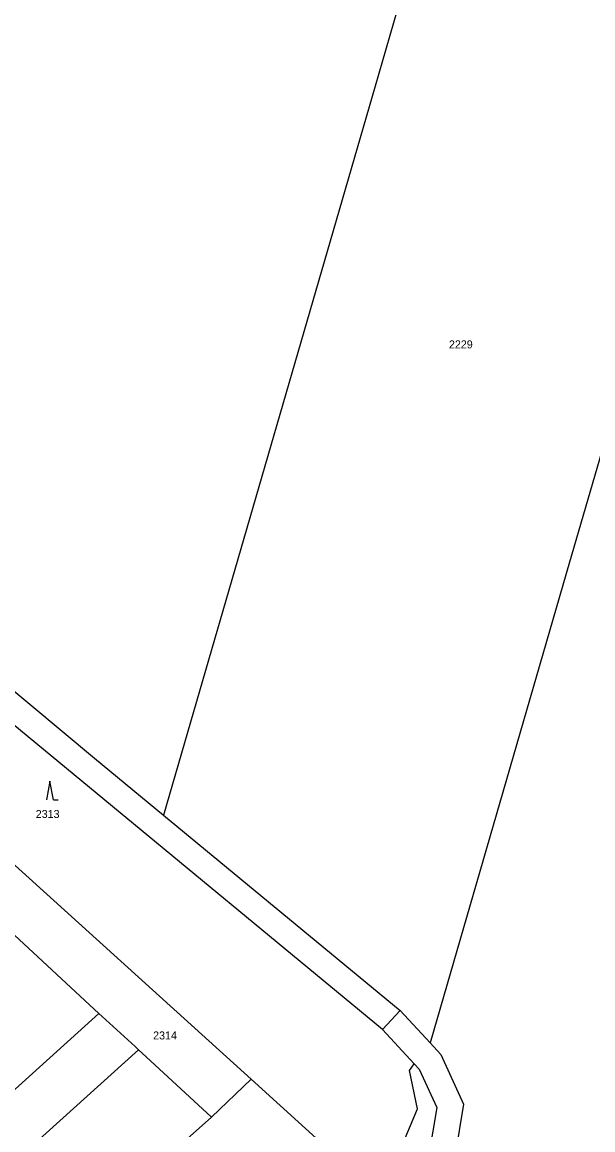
# Model space of a CAD drawing. Extents: x -606517 to -602431, y -1183120 to -1179397.
# Drawn here: x -604814.8 to -604693.5, y -1180857.3 to -1180622.1 of the extents above; entities that cross this region are included whole.
import ezdxf

# ---------------------------------------------------------------- set-up
doc = ezdxf.new("R2010")
doc.units = 0
doc.header["$LTSCALE"] = 0.68
doc.layers.add('1', color=7, linetype='Continuous', lineweight=25)
doc.layers.add('3', color=7, linetype='Continuous', lineweight=25)
doc.layers.add('2', color=7, linetype='Continuous')

msp = doc.modelspace()

# ---------------------------------------------------------------- linework, layer by layer
at = {"layer": '1'}
for p, q in [((-604694.81, -1180480.93), (-604739.79, -1180635.68)), ((-604668.76, -1180634.63), (-604698.43, -1180736.72)), ((-604739.79, -1180635.68), (-604784.77, -1180790.44)), ((-604870.51, -1180719.22), (-604799.44, -1180778.35)), ((-604698.43, -1180736.72), (-604728.1, -1180838.8)), ((-604803.76, -1180781.91), (-604851.37, -1180742.57)), ((-604799.44, -1180778.35), (-604784.77, -1180790.44)), ((-604738.23, -1180835.98), (-604803.76, -1180781.91)), ((-604836.32, -1180783.1), (-604766.15, -1180846.54)), ((-604784.77, -1180790.44), (-604734.45, -1180831.97)), ((-604817.43, -1180815.05), (-604798.46, -1180832.55)), ((-604734.45, -1180831.97), (-604738.23, -1180835.98)), ((-604734.45, -1180831.97), (-604728.1, -1180838.8)), ((-604883.82, -1180909.45), (-604798.46, -1180832.55)), ((-604798.46, -1180832.55), (-604797.75, -1180833.2)), ((-604797.75, -1180833.2), (-604790.79, -1180839.62)), ((-604731.46, -1180843.26), (-604738.23, -1180835.98)), ((-604728.1, -1180838.8), (-604725.77, -1180841.3)), ((-604874.53, -1180916.36), (-604790.07, -1180840.29)), ((-604790.79, -1180839.62), (-604790.07, -1180840.29)), ((-604790.07, -1180840.29), (-604789.38, -1180840.92)), ((-604789.38, -1180840.92), (-604774.54, -1180854.61)), ((-604725.77, -1180841.3), (-604720.96, -1180851.82)), ((-604732.48, -1180844.7), (-604731.46, -1180843.26)), ((-604731.46, -1180843.26), (-604730.4, -1180844.4)), ((-604730.74, -1180852.82), (-604732.48, -1180844.7)), ((-604730.4, -1180844.4), (-604726.66, -1180852.57)), ((-604766.15, -1180846.54), (-604774.54, -1180854.61)), ((-604766.15, -1180846.54), (-604739.14, -1180870.96)), ((-604737.64, -1180869.05), (-604730.74, -1180852.82)), ((-604726.66, -1180852.57), (-604728.49, -1180863.44)), ((-604720.96, -1180851.82), (-604723.21, -1180865.2)), ((-604774.54, -1180854.61), (-604812.16, -1180887.79))]:
    msp.add_line(p, q, dxfattribs=at)
at = {"layer": '3'}
msp.add_line((-604808.15, -1180787.25), (-604807.154, -1180787.25), dxfattribs=at)
msp.add_lwpolyline([(-604808.15, -1180787.25), (-604808.9, -1180783.25), (-604809.65, -1180787.25)], dxfattribs=at)

# ---------------------------------------------------------------- texts
at = {"layer": '2'}
for s, p in [('2229', (-604724.08, -1180691.355)), ('2313', (-604811.9, -1180791.075)), ('2314', (-604786.96, -1180838.095))]:
    msp.add_text(s, height=1.7, dxfattribs=at).set_placement(p)

doc.saveas('drawing.dxf')
